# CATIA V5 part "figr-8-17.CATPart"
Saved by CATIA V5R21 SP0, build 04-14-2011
Part number: Part1
Bounding box of the stored display mesh (mm): x -55.501 to 55.501, y -84.223 to 84.223, z 0 to 81
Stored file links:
  D:\CATIA V5R21 E-RESOURCES\CATIA-V5R21\catia-v5r21-prt\c08-catia-v5r20-prt\c08-catia-v5r21-figr-8-17.CATPart
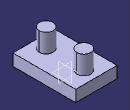
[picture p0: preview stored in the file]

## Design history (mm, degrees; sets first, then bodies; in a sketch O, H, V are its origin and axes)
Body1 (main body)
  Sketch1 on xy-plane, origin (0, 0, 0), H (1, 0, 0), V (0, 1, 0)
    line L1 (-55.501, 84.2232) -> (55.501, 84.2232)
    line L2 (55.501, 84.2232) -> (55.501, -84.2232)
    line L3 (55.501, -84.2232) -> (-55.501, -84.2232)
    line L4 (-55.501, -84.2232) -> (-55.501, 84.2232)
    axis line L5 (55.501, -84.2232) -> (-55.501, 84.2232)
    horizontal: L1 H, L3 H
    vertical: L2 V, L4 V
    midpoint: O L5
  Pad1: profile Sketch1, direction (0, 0, 1), length 31
  Sketch2 on face of Pad1, origin (0, 0, 31), H (1, 0, 0), V (0, 1, 0)
    circle A1 centre (0, -50.4568) radius 18.9426
    point P1 (0, -50.4568)
    coincidence: P1 V
  Pad2: profile Sketch2, direction (0, 0, 1), length 50
  Mirror1: of Pad2, Sketch2, about zx-plane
